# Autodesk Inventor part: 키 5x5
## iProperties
Created: 2014-10
Part Number: 키 5x5
Document SubType Name: Modeling
Designer: KYOUNG IL JANG
Density: 1 g/cm^3
Mass: 0.323175 g
Surface Area: 2.9781 cm^2
Volume: 0.323175 cm^3
Author: SeoGD™ [www.esajin.kr]
Revision Number: 1
